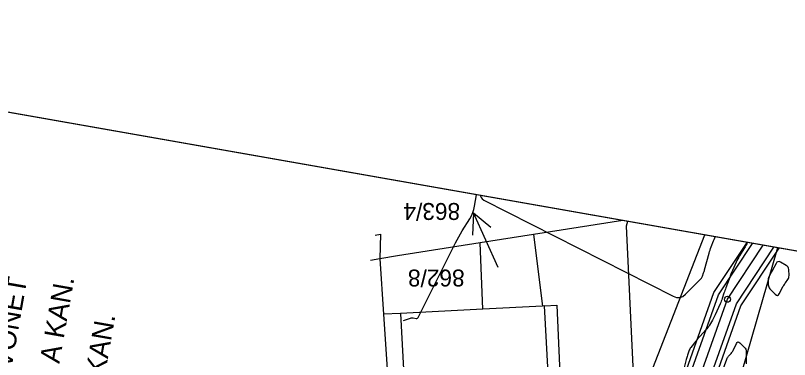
# Model space of a CAD drawing. Extents: x -534481 to -534262, y -1190577 to -1190138.
# Drawn here: x -534379.97 to -534341.14, y -1190154.95 to -1190137.67 of the extents above; entities that cross this region are included whole.
import ezdxf

# ---------------------------------------------------------------- set-up
doc = ezdxf.new("R2010")
doc.units = 0
for name, color, linetype in [('Bonity', 7, 'Continuous'), ('Definiční body', 7, 'Continuous'), ('OMP', 7, 'Continuous'), ('Polygon budovy', 7, 'Continuous'), ('Polygon parcely', 7, 'Continuous'), ('Vrstva 18', 7, 'Continuous'), ('Vrstva 19', 7, 'Continuous'), ('Vrstva 30', 7, 'Continuous'), ('Vrstva 35', 7, 'Continuous'), ('Vrstva 37', 7, 'Continuous'), ('Vrstva 43', 7, 'Continuous'), ('Vrstva 47', 7, 'Continuous')]:
    doc.layers.add(name, color=color, linetype=linetype)

msp = doc.modelspace()

# ---------------------------------------------------------------- linework, layer by layer
at = {"layer": 'Bonity'}
msp.add_lwpolyline([(-534342.428, -1190234.65), (-534342.865, -1190226.62), (-534344.323, -1190207.198), (-534345.257, -1190192.285), (-534345.89, -1190175.458), (-534346.05, -1190156.962), (-534344.257, -1190151.926), (-534342.463, -1190149.215)], dxfattribs=at)
at = {"layer": 'Definiční body'}
for p, q in [((-534349.508, -1190147.972), (-534353.99, -1190148.68)), ((-534353.99, -1190148.68), (-534356.66, -1190149.1)), ((-534353.99, -1190148.68), (-534353.54, -1190152.27)), ((-534356.53, -1190152.42), (-534356.66, -1190149.1)), ((-534361.7, -1190149.89), (-534362.153, -1190149.978)), ((-534361.7, -1190149.89), (-534361.51, -1190152.68)), ((-534353.54, -1190152.27), (-534356.53, -1190152.42)), ((-534353.43, -1190152.26), (-534353.54, -1190152.27))]:
    msp.add_line(p, q, dxfattribs=at)
for points in [[(-534349.263, -1190148.015), (-534349.33, -1190148.26), (-534348.67, -1190162.35), (-534348.64, -1190164.35), (-534348.75, -1190166.39), (-534349.02, -1190168.37), (-534349.42, -1190170.33), (-534353.85, -1190185.89), (-534354.6, -1190189.86), (-534354.75, -1190192.89), (-534354.73, -1190197.08)], [(-534361.93, -1190148.713), (-534361.66, -1190148.66), (-534361.7, -1190149.89)], [(-534347.19, -1190196.18), (-534347.17, -1190176.21), (-534348.39, -1190156.38), (-534345.398, -1190148.697)], [(-534356.66, -1190149.1), (-534360.81, -1190149.75), (-534361.7, -1190149.89)], [(-534341.743, -1190149.341), (-534343.82, -1190156.54), (-534343.24, -1190185.5)], [(-534356.05, -1190164.42), (-534352.78, -1190164.24), (-534353.43, -1190152.26)], [(-534353.43, -1190152.26), (-534352.82, -1190152.23), (-534352.3, -1190164.02), (-534352.41, -1190166), (-534352.72, -1190168), (-534353.15, -1190169.96), (-534355.5, -1190178.16)], [(-534356.53, -1190152.42), (-534360.66, -1190152.64), (-534361.51, -1190152.68)], [(-534361.51, -1190152.68), (-534361.14, -1190158.2), (-534360.62, -1190167.61)]]:
    msp.add_lwpolyline(points, dxfattribs=at)
at = {"layer": 'Polygon parcely'}
msp.add_lwpolyline([(-534359.85, -1190167.58), (-534356.61, -1190167.47), (-534356.7, -1190164.46), (-534356.05, -1190164.42), (-534352.78, -1190164.24), (-534353.43, -1190152.26), (-534353.54, -1190152.27), (-534356.53, -1190152.42), (-534360.66, -1190152.64)], close=True, dxfattribs=at)
at = {"layer": 'Vrstva 18'}
msp.add_lwpolyline([(-534343.253, -1190149.075), (-534343.29, -1190149.144), (-534343.318, -1190149.193), (-534343.346, -1190149.242), (-534343.374, -1190149.291), (-534343.404, -1190149.34), (-534343.649, -1190149.741), (-534343.695, -1190149.818), (-534343.738, -1190149.897), (-534343.779, -1190149.976), (-534343.817, -1190150.057), (-534344.008, -1190150.476), (-534344.024, -1190150.511), (-534344.039, -1190150.548), (-534344.053, -1190150.584), (-534344.065, -1190150.621), (-534344.115, -1190150.77), (-534344.127, -1190150.807), (-534344.14, -1190150.844), (-534344.154, -1190150.881), (-534344.168, -1190150.918), (-534344.336, -1190151.357), (-534344.361, -1190151.423), (-534344.385, -1190151.489), (-534344.409, -1190151.555), (-534344.431, -1190151.622), (-534344.52, -1190151.889), (-534344.543, -1190151.956), (-534344.568, -1190152.022), (-534344.595, -1190152.087), (-534344.623, -1190152.151), (-534344.877, -1190152.71), (-534344.909, -1190152.777), (-534344.941, -1190152.843), (-534344.976, -1190152.908), (-534345.012, -1190152.972), (-534345.159, -1190153.227), (-534345.198, -1190153.29), (-534345.24, -1190153.35), (-534345.285, -1190153.407), (-534345.334, -1190153.462), (-534345.627, -1190153.774), (-534345.684, -1190153.836), (-534345.74, -1190153.9), (-534345.794, -1190153.964), (-534345.846, -1190154.031), (-534346.089, -1190154.346), (-534346.12, -1190154.39), (-534346.147, -1190154.436), (-534346.171, -1190154.485), (-534346.19, -1190154.535), (-534346.26, -1190154.741), (-534346.277, -1190154.793), (-534346.294, -1190154.845), (-534346.309, -1190154.897), (-534346.323, -1190154.95), (-534346.461, -1190155.487)], dxfattribs=at)
at = {"layer": 'Vrstva 19'}
for points in [[(-534360.503, -1190152.994), (-534360.156, -1190152.869), (-534360.121, -1190152.859), (-534360.086, -1190152.854), (-534360.051, -1190152.854), (-534360.015, -1190152.859), (-534359.872, -1190152.887), (-534359.838, -1190152.889), (-534359.81, -1190152.881), (-534359.786, -1190152.864), (-534359.767, -1190152.836), (-534357.9, -1190149.097), (-534357.82, -1190148.941), (-534357.736, -1190148.787), (-534357.648, -1190148.635), (-534357.557, -1190148.484), (-534357.185, -1190147.887), (-534357.099, -1190147.735), (-534357.03, -1190147.577), (-534356.975, -1190147.413), (-534356.937, -1190147.243), (-534356.837, -1190146.68)], [(-534356.652, -1190146.713), (-534356.651, -1190146.726), (-534356.617, -1190146.814), (-534356.556, -1190146.887), (-534356.47, -1190146.945), (-534346.982, -1190151.777), (-534346.812, -1190151.837), (-534346.651, -1190151.841), (-534346.5, -1190151.787), (-534346.358, -1190151.677), (-534345.591, -1190150.904), (-534345.563, -1190150.873), (-534345.54, -1190150.84), (-534345.521, -1190150.804), (-534345.506, -1190150.765), (-534345.453, -1190150.607), (-534345.44, -1190150.568), (-534345.428, -1190150.528), (-534345.416, -1190150.488), (-534345.405, -1190150.448), (-534345.179, -1190149.609), (-534345.157, -1190149.53), (-534345.132, -1190149.453), (-534345.105, -1190149.376), (-534345.076, -1190149.299), (-534344.955, -1190148.996), (-534344.925, -1190148.92), (-534344.898, -1190148.843), (-534344.879, -1190148.788)], [(-534344.523, -1190155.574), (-534344.293, -1190154.931), (-534344.276, -1190154.889), (-534344.254, -1190154.849), (-534344.229, -1190154.812), (-534344.2, -1190154.777), (-534344.075, -1190154.642), (-534344.045, -1190154.607), (-534344.019, -1190154.571), (-534343.994, -1190154.532), (-534343.973, -1190154.492), (-534343.807, -1190154.144), (-534343.772, -1190154.093), (-534343.733, -1190154.07), (-534343.688, -1190154.077), (-534343.637, -1190154.114), (-534343.396, -1190154.347), (-534343.363, -1190154.386), (-534343.339, -1190154.429), (-534343.325, -1190154.476), (-534343.322, -1190154.527), (-534343.326, -1190154.739), (-534343.326, -1190154.792), (-534343.326, -1190154.844), (-534343.326, -1190154.897), (-534343.324, -1190154.95), (-534343.318, -1190155.166)]]:
    msp.add_lwpolyline(points, dxfattribs=at)
msp.add_lwpolyline([(-534341.193, -1190150.364), (-534341.218, -1190150.308), (-534341.257, -1190150.261), (-534341.31, -1190150.224), (-534341.605, -1190150.062), (-534341.67, -1190150.038), (-534341.727, -1190150.04), (-534341.776, -1190150.07), (-534341.817, -1190150.126), (-534341.999, -1190150.473), (-534342.019, -1190150.51), (-534342.04, -1190150.548), (-534342.061, -1190150.586), (-534342.083, -1190150.623), (-534342.171, -1190150.771), (-534342.19, -1190150.808), (-534342.204, -1190150.848), (-534342.211, -1190150.888), (-534342.214, -1190150.931), (-534342.211, -1190151.194), (-534342.205, -1190151.25), (-534342.189, -1190151.303), (-534342.164, -1190151.351), (-534342.129, -1190151.395), (-534341.86, -1190151.677), (-534341.804, -1190151.721), (-534341.752, -1190151.731), (-534341.705, -1190151.708), (-534341.662, -1190151.651), (-534341.455, -1190151.273), (-534341.429, -1190151.228), (-534341.403, -1190151.184), (-534341.374, -1190151.141), (-534341.345, -1190151.098), (-534341.226, -1190150.929), (-534341.2, -1190150.886), (-534341.182, -1190150.84), (-534341.172, -1190150.792), (-534341.17, -1190150.741), (-534341.183, -1190150.429)], close=True, dxfattribs=at)
at = {"layer": 'Vrstva 30'}
msp.add_line((-534261.668, -1190163.461), (-534407.912, -1190137.674), dxfattribs=at)
msp.add_lwpolyline([(-534261.668, -1190163.461), (-534407.912, -1190137.674), (-534426.145, -1190241.079), (-534279.901, -1190266.866)], dxfattribs=at)
at = {"layer": 'Vrstva 35'}
for points in [[(-534343.317, -1190232.109), (-534343.613, -1190226.668), (-534345.072, -1190207.25), (-534346.006, -1190192.323), (-534346.64, -1190175.475), (-534346.801, -1190156.835), (-534344.933, -1190151.588), (-534343.268, -1190149.073)], [(-534343.067, -1190232.098), (-534343.364, -1190226.652), (-534344.822, -1190207.233), (-534345.756, -1190192.31), (-534346.39, -1190175.47), (-534346.551, -1190156.878), (-534344.708, -1190151.701), (-534343, -1190149.12)], [(-534342.068, -1190232.057), (-534342.366, -1190226.587), (-534343.825, -1190207.164), (-534344.757, -1190192.26), (-534345.39, -1190175.446), (-534345.55, -1190157.046), (-534343.807, -1190152.151), (-534341.926, -1190149.309)], [(-534341.818, -1190232.046), (-534342.116, -1190226.571), (-534343.575, -1190207.147), (-534344.507, -1190192.248), (-534345.14, -1190175.441), (-534345.299, -1190157.088), (-534343.581, -1190152.264), (-534341.657, -1190149.357)]]:
    msp.add_lwpolyline(points, dxfattribs=at)
at = {"layer": 'Vrstva 37'}
msp.add_circle((-534344.257, -1190151.926), 0.15, dxfattribs=at)
msp.add_circle((-534344.257, -1190151.926), 0.15, dxfattribs=at)
msp.add_circle((-534344.257, -1190151.926), 0.15, dxfattribs=at)
msp.add_circle((-534344.257, -1190151.926), 0.15, dxfattribs=at)
msp.add_circle((-534344.257, -1190151.926), 0.15, dxfattribs=at)
msp.add_circle((-534344.257, -1190151.926), 0.15, dxfattribs=at)
at = {"layer": 'Vrstva 43'}
msp.add_line((-534261.668, -1190163.461), (-534407.912, -1190137.674), dxfattribs=at)
at = {"layer": 'Vrstva 47'}
for p, q in [((-534356.987, -1190147.586), (-534357.037, -1190148.705)), ((-534355.766, -1190150.328), (-534356.987, -1190147.586)), ((-534356.987, -1190147.586), (-534356.122, -1190148.298))]:
    msp.add_line(p, q, dxfattribs=at)

# ---------------------------------------------------------------- texts
at = {"layer": 'OMP'}
for s, p in [('TELEKOMUNIKAČNÍ KABEL - AVONET', (-534383.565, -1190174.687)), ('KANALIZACE - SLOVÁCKÉ VDV A KAN.', (-534381.281, -1190175.09)), ('VODOVOD - SLOVÁCKÉ VDV A KAN.', (-534378.962, -1190175.499))]:
    msp.add_text(s, height=1, rotation=79.9998, dxfattribs=at).set_placement(p)
at = {"layer": 'Polygon budovy'}
for s, p in [('863/4', (-534357.665, -1190147.093)), ('862/8', (-534357.44, -1190150.435))]:
    msp.add_text(s, height=0.85, rotation=180, dxfattribs=at).set_placement(p)

doc.saveas('drawing.dxf')
